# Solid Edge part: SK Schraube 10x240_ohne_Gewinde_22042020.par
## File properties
Author: fknapp
Template: Normal.par
Last saved by: fknapp
Revision: 25
Application: Solid Edge
Username: fknapp
Material: Aluminium
Genauigkeit: 0,99
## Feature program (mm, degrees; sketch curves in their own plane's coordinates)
sketch for "unnamed RevolvedProtrusion 1" plane through (0, 0, 0) normal (0, 0, 1) x-axis (1, 0, 0)
  line (0, 54) -> (9, 54)
  line (9, 54) -> (9, 53)
  line (9, 53) -> (5, 49)
  line (5, 49) -> (5, 46.3)
  line (5, 46.3) -> (4.7548, 46.3)
  arc centre (4.7548, 44.6952) radius 1.6048 from (4.7548, 46.3) to (3.15, 44.6952) ccw
  line (3.15, 44.6952) -> (3.15, 42)
  line (3.15, 42) -> (5, 42)
  line (5, -173) -> (5, 42)
  line (0.5, -186) -> (5, -173)
  line (0, -186) -> (0.5, -186)
revolve "unnamed RevolvedProtrusion 1" add full turn 360 deg about sketch line (0, 54) -> (0, -186)
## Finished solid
Body 1: solid body, 11 faces, 10 edges, 0 vertices.
  Faces by surface: cylinder 4, plane 4, cone 2, torus 1
  Edges by curve: circle 10
Bounding box of the edges (mm; curved faces can reach further): 18.000 x 240.000 x 18.000, from (-9, -186, -9) to (9, 54, 9).
Cylindrical faces by radius (mm): R3.15 x1, R5 x2, R9 x1
Conical faces (half-angle, radius in mm at the cone's reference point): 19.0935 deg R5 x1, 45 deg R9 x1
Toroidal faces (ring radius, tube radius in mm): R4.7548 r1.6048 x1
Planar faces by outward normal: +y 2, -y 2
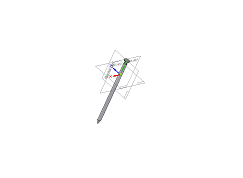
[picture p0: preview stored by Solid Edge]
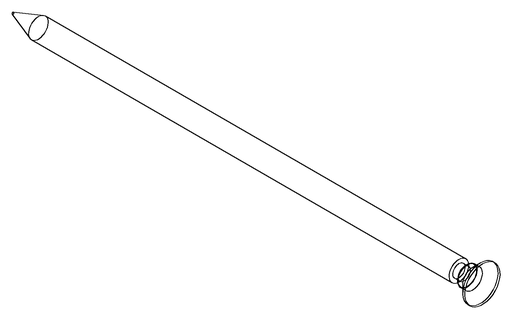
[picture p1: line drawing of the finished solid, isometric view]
